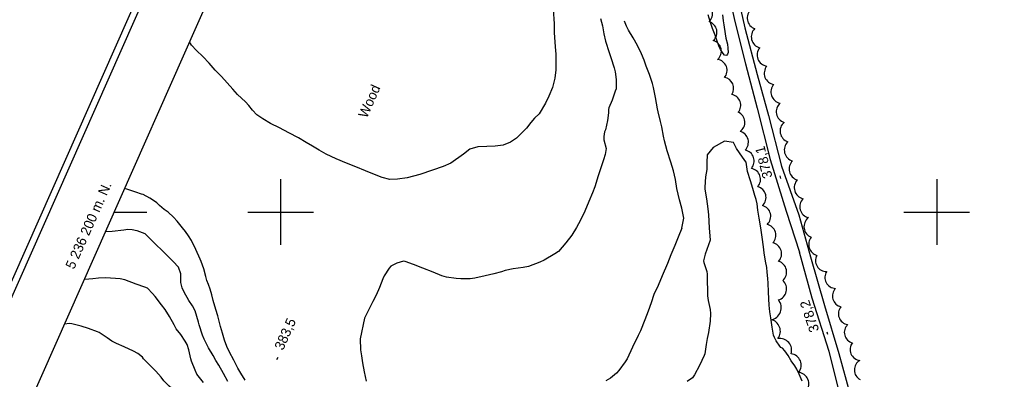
# Model space of a CAD drawing. Extents: x 287698 to 290158, y 5234163 to 5237182.
# Drawn here: x 288320.4 to 288616.1, y 5236148.9 to 5236258.8 of the extents above; entities that cross this region are included whole.
import ezdxf

# ---------------------------------------------------------------- set-up
doc = ezdxf.new("R2010")
doc.units = 0
for name, color, linetype in [('Niveau 1', 7, 'Continuous'), ('Niveau 19', 7, 'Continuous'), ('Niveau 2', 7, 'Continuous'), ('Niveau 3', 7, 'Continuous'), ('Niveau 44', 7, 'Continuous'), ('Niveau 60', 7, 'Continuous'), ('Niveau 61', 7, 'Continuous')]:
    doc.layers.add(name, color=color, linetype=linetype)

msp = doc.modelspace()

# ---------------------------------------------------------------- linework, layer by layer
at = {"layer": 'Niveau 1'}
for points in [[(288534.72, 5236260.25), (288534.91, 5236258.33), (288535.1, 5236257.1), (288535.48, 5236254.44), (288535.74, 5236253.1), (288536.18, 5236251.2), (288536.33, 5236249.99), (288536.38, 5236248.73), (288536.2, 5236248.19), (288535.88, 5236247.74), (288535.34, 5236247.84), (288534.88, 5236248.4), (288534.13, 5236249.61), (288533.62, 5236250.69), (288532.93, 5236252.42), (288532.41, 5236253.98), (288531.66, 5236256.01), (288530.93, 5236258.13), (288530.27, 5236260.25)], [(288522.32, 5236195.12), (288522.93, 5236198.1), (288522.25, 5236201.2), (288521.58, 5236203.71), (288520.78, 5236207.22), (288520.32, 5236209.96), (288519.72, 5236212.64), (288518.98, 5236215.22), (288517.8, 5236218.65), (288516.98, 5236221.74), (288516.71, 5236223.13), (288516.23, 5236226.05), (288515.83, 5236227.65), (288515.03, 5236230.64), (288514.89, 5236231.52), (288514.27, 5236235.01), (288513.7, 5236238), (288513.37, 5236239.23), (288512.39, 5236242), (288511.44, 5236244.53), (288510.86, 5236246.34), (288510.02, 5236248.34), (288508.79, 5236250.83), (288507.44, 5236253.16), (288506.05, 5236255.48), (288505.46, 5236256.78), (288504.83, 5236258.24)], [(288522.32, 5236195.12), (288521.19, 5236192.34), (288520.13, 5236189.76), (288518.98, 5236186.94), (288517.89, 5236184.28), (288516.33, 5236180.53), (288515.04, 5236177.63), (288513.76, 5236174.8), (288512.94, 5236172.31), (288511.99, 5236169.78), (288510.99, 5236167.09), (288509.71, 5236163.8), (288509, 5236162.3), (288507.29, 5236158.74), (288505.62, 5236155.22), (288505, 5236154.26), (288503.13, 5236151.62), (288502.38, 5236150.82), (288500.53, 5236149.36), (288499.11, 5236148.54)], [(288346.56, 5236194.05), (288348.62, 5236194.21), (288352.22, 5236194.55), (288353.37, 5236194.77), (288354.78, 5236194.69), (288356.15, 5236194.36), (288358.61, 5236193.49), (288367.23, 5236184.96)], [(288383.86, 5236148.34), (288382.57, 5236150.76), (288381.17, 5236153.28), (288380.2, 5236154.74), (288379.4, 5236156.22), (288378.03, 5236158.6), (288376.72, 5236161.19), (288376.2, 5236162.43), (288375.11, 5236165.63), (288374.92, 5236166.41), (288373.92, 5236169.86), (288373.08, 5236171.39), (288372.01, 5236173.01), (288370.6, 5236175.51), (288369.97, 5236176.92), (288369.58, 5236178.49), (288369.56, 5236181.16), (288368.87, 5236183.24), (288367.23, 5236184.96)]]:
    msp.add_lwpolyline(points, dxfattribs=at)
at = {"layer": 'Niveau 19'}
for points in [[(288518.52, 5236482.17), (288518.51, 5236469.32), (288517.92, 5236453.86), (288517.66, 5236437.54), (288517.23, 5236421.32), (288517.22, 5236403.64), (288518.39, 5236388.14), (288519.01, 5236373.22), (288520.62, 5236356.96), (288521.68, 5236343.74), (288523.2, 5236324.51), (288526.18, 5236307.64), (288529.13, 5236294.92), (288532.36, 5236282.96), (288535.67, 5236270.53), (288538.48, 5236258.13), (288541.67, 5236245.25), (288545.24, 5236231.69), (288549.17, 5236216.09), (288554.11, 5236200.24), (288558.19, 5236187.81)], [(288521.3, 5236480.92), (288520.93, 5236467.19), (288520.46, 5236451.28), (288519.89, 5236435.79), (288519.6, 5236421.45), (288519.87, 5236405.37), (288520.97, 5236389.91), (288521.87, 5236372.23), (288522.99, 5236355.92), (288524.29, 5236339.04), (288526.08, 5236323.71), (288528.12, 5236311.11), (288530.98, 5236297.47), (288534.85, 5236283.63), (288538.06, 5236271.56), (288541.5, 5236256.24), (288545.27, 5236242), (288548.74, 5236229.5), (288552.67, 5236214.05), (288558.01, 5236199.12), (288561.49, 5236186.39)], [(288579.45, 5235966.21), (288590.48, 5235970.55), (288599.56, 5235973.1), (288608.8, 5235975.7), (288611.76, 5235977.65), (288611, 5235981.11), (288607.75, 5235989.15), (288602.54, 5236003.05), (288600.44, 5236015.05), (288597.95, 5236030.93), (288595.07, 5236045.76), (288591.11, 5236062.15), (288585.16, 5236080.73), (288580.85, 5236098.75), (288577.18, 5236115.66), (288572.06, 5236138.02), (288567.19, 5236157.42), (288562.05, 5236173.75), (288558.19, 5236187.81)], [(288561.49, 5236186.39), (288565.78, 5236171.53), (288570.11, 5236156.8), (288574.67, 5236140.56)]]:
    msp.add_lwpolyline(points, dxfattribs=at)
at = {"layer": 'Niveau 2'}
for points in [[(288483.03, 5236261.92), (288483.34, 5236257.49), (288483.38, 5236254.85), (288483.67, 5236250.39), (288483.87, 5236248.22), (288483.87, 5236243.38), (288483.6, 5236240.9), (288482.85, 5236238), (288481.77, 5236235.34), (288480.72, 5236233.27), (288478.77, 5236229.97), (288477.4, 5236228.67), (288476.27, 5236227.37), (288474.99, 5236225.65), (288471.93, 5236222.55), (288470.02, 5236221.35), (288467.81, 5236220.45), (288465.4, 5236220.07), (288462.84, 5236219.99), (288460.15, 5236219.91), (288457.68, 5236219.19), (288455.69, 5236217.63), (288451.9, 5236214.93), (288449.57, 5236213.92), (288446.28, 5236212.77), (288442.39, 5236211.5), (288438.56, 5236210.42), (288435.65, 5236210.04), (288433.28, 5236209.96), (288430.97, 5236210.58), (288428.61, 5236211.48)], [(288497.51, 5236259.04), (288498.12, 5236256.83), (288498.54, 5236254.36), (288499.03, 5236252.17), (288500.11, 5236248.71), (288500.68, 5236247.13), (288501.7, 5236244.06), (288502, 5236242.82), (288502.25, 5236240.47), (288502.28, 5236237.64), (288501.98, 5236236.91), (288501.03, 5236234.12), (288500.08, 5236231.81), (288499.9, 5236231.35)], [(288428.61, 5236211.48), (288425.9, 5236212.59), (288422.95, 5236213.76), (288420.04, 5236214.95), (288416.89, 5236216.24), (288413.82, 5236217.66), (288411.7, 5236218.85), (288409.74, 5236220.13), (288407.78, 5236221.21), (288405.41, 5236222.64), (288402.5, 5236224.21), (288399.64, 5236225.74), (288396.91, 5236227), (288394.59, 5236228.44), (288392.78, 5236229.72), (288391.39, 5236231.12), (288390.34, 5236232.54), (288389.24, 5236233.6), (288386.89, 5236235.91), (288385.45, 5236237.56), (288381.93, 5236241.34), (288380.02, 5236243.32), (288378.19, 5236245.49), (288376.24, 5236247.47), (288374.32, 5236249.28), (288372.84, 5236250.98), (288372.22, 5236252.01)], [(288499.9, 5236231.35), (288499.89, 5236230.3), (288499.62, 5236227.94), (288499.03, 5236225.08), (288498.74, 5236224.52), (288498.51, 5236223.02), (288498.54, 5236222.01), (288499.19, 5236219.37), (288498.9, 5236217.57), (288498.38, 5236215.99), (288496.83, 5236211.08), (288495.78, 5236207.74), (288495.08, 5236205.87), (288493.92, 5236203.18), (288492.68, 5236200.26), (288491.38, 5236197.55), (288490.22, 5236195.31), (288488.74, 5236192.97), (288486.97, 5236190.58), (288484.71, 5236188.02), (288483.6, 5236187.29), (288480.37, 5236185.34), (288478.99, 5236184.69), (288475.53, 5236183.44), (288473.96, 5236183.13), (288470.86, 5236182.69), (288468.39, 5236182.21), (288467.32, 5236181.77), (288464.94, 5236181.12), (288462.38, 5236180.59), (288459.22, 5236179.87), (288457.75, 5236179.67), (288454.95, 5236179.64), (288453.45, 5236179.73), (288450.55, 5236180.15), (288449.17, 5236180.55), (288446.46, 5236181.66)], [(288541.91, 5236215.21), (288541.84, 5236215.29), (288540.79, 5236216.71), (288538.97, 5236219.43), (288538.08, 5236221.27), (288535.28, 5236221.69), (288531.85, 5236219.73)], [(288531.85, 5236219.73), (288529.98, 5236217.46), (288529.9, 5236215.16), (288529.88, 5236213), (288529.46, 5236210.76), (288529.34, 5236207.58), (288529.32, 5236206.98), (288529.78, 5236204.04), (288530.26, 5236200.97), (288530.4, 5236199.14), (288530.63, 5236195.15), (288530.92, 5236191.47), (288530.47, 5236189.99), (288529.38, 5236187.17), (288528.91, 5236185.15), (288528.99, 5236184.57), (288529.87, 5236181.85), (288530.02, 5236181.05), (288530.05, 5236178.95), (288530.13, 5236176.13), (288530.08, 5236174.39), (288530.27, 5236172.97), (288530.88, 5236170.31), (288530.99, 5236169.03), (288530.93, 5236166.67), (288530.42, 5236163.23), (288530, 5236161.42), (288529.72, 5236159.56), (288529.29, 5236156.72), (288529.1, 5236156.26), (288527.63, 5236153.14), (288526.2, 5236150.36), (288525.57, 5236149.44), (288523.94, 5236148.33)], [(288550.27, 5236162.42), (288549.82, 5236164.92), (288549.65, 5236166.28), (288549.38, 5236167.7), (288549.1, 5236169.6), (288548.9, 5236171.63), (288548.78, 5236173.51), (288548.71, 5236175.68), (288548.63, 5236178.26), (288548.47, 5236179.72), (288548.34, 5236181.63), (288548.16, 5236183.04), (288547.83, 5236185.03), (288547.41, 5236187.55), (288547.21, 5236189.39), (288546.79, 5236192.38), (288546.33, 5236195.23), (288545.89, 5236198.15), (288545.49, 5236200.56), (288545.21, 5236202.51), (288544.93, 5236203.81), (288544.59, 5236205.07), (288543.97, 5236207.21), (288543.24, 5236209.58), (288542.35, 5236212.4), (288542.06, 5236213.78), (288541.91, 5236215.21)], [(288389.13, 5236148.7), (288387.81, 5236150.83), (288386.98, 5236152.41), (288385.7, 5236154.82), (288384.41, 5236157.2), (288383.58, 5236159), (288382.83, 5236160.96), (288382.23, 5236163.01), (288381.7, 5236165.11), (288380.89, 5236168.3), (288380.28, 5236170.3), (288379.44, 5236173.03), (288379.01, 5236174.79), (288378.54, 5236176.52), (288377.96, 5236177.85), (288377.48, 5236179.16), (288377.16, 5236180.38), (288376.53, 5236182.63), (288375.81, 5236184.93), (288375.47, 5236185.65), (288374.09, 5236188.57), (288372.77, 5236191.32), (288371.89, 5236192.74), (288371, 5236194.03), (288370.07, 5236195.22), (288368.47, 5236197.22), (288367.31, 5236198.44), (288365.67, 5236200.01), (288364.51, 5236200.83), (288363.02, 5236201.96), (288362.23, 5236202.83), (288361.23, 5236203.58), (288360.08, 5236204.21), (288358.1, 5236205.34), (288357.6, 5236205.48), (288355.84, 5236206.1), (288353.1, 5236207.03), (288352.37, 5236207.17)], [(288446.46, 5236181.66), (288443.34, 5236182.9), (288440.54, 5236184.02), (288437.94, 5236184.96), (288437.44, 5236185), (288435.46, 5236184.46), (288433.56, 5236183.49), (288433.04, 5236182.93), (288431.54, 5236180.59), (288431.13, 5236179.67), (288430.09, 5236176.96), (288429.14, 5236174.63), (288428.14, 5236172.76)], [(288376.47, 5236147.97), (288374.46, 5236150.58), (288373.91, 5236151.74), (288372.81, 5236154.53), (288372.62, 5236155.25), (288372.03, 5236157.95), (288371.5, 5236159.55), (288370.9, 5236160.65), (288369.57, 5236162.67), (288368.19, 5236164.36), (288367.55, 5236165.55), (288366.14, 5236168.11), (288364.78, 5236170.23), (288363.68, 5236171.74), (288361.77, 5236174.25), (288360.95, 5236175.17), (288359.36, 5236176.75), (288358.56, 5236177.07), (288355.93, 5236178.02), (288352.48, 5236179.34), (288351.04, 5236179.67), (288349.67, 5236179.75), (288346.56, 5236179.93), (288344.49, 5236179.88), (288342.75, 5236179.6), (288340.29, 5236179.39), (288340.08, 5236179.4)], [(288428.14, 5236172.76), (288425.6, 5236167.59), (288424.28, 5236161.27), (288424.31, 5236157.96), (288424.68, 5236156.15), (288424.97, 5236154.04), (288425.43, 5236151.29), (288426.1, 5236148.35)], [(288372.51, 5236141.2), (288371.89, 5236141.71), (288369.73, 5236143.39), (288368.41, 5236144.7), (288366.04, 5236146.83), (288364.4, 5236148.52), (288363.57, 5236149.63), (288361.97, 5236151.44), (288360.13, 5236153.28), (288358.2, 5236155.22), (288357.86, 5236155.71), (288356.42, 5236156.8), (288355.15, 5236157.53), (288352.28, 5236158.89), (288349.94, 5236159.91), (288348.56, 5236160.62), (288347.06, 5236161.67), (288344.67, 5236163.25), (288344.12, 5236163.47), (288341.46, 5236164.47), (288339.19, 5236165.2), (288336.35, 5236165.91), (288335.64, 5236165.99), (288334.07, 5236165.83)], [(288559.02, 5236148.37), (288558.08, 5236150.53), (288557.3, 5236152.09), (288556.7, 5236153.07), (288555.64, 5236154.62), (288554.7, 5236156.2), (288553.67, 5236157.69), (288552.95, 5236158.47), (288552.48, 5236158.69), (288552.14, 5236159.12), (288551.1, 5236160.66), (288550.53, 5236161.69), (288550.27, 5236162.42)]]:
    msp.add_lwpolyline(points, dxfattribs=at)
at = {"layer": 'Niveau 3'}
for p, q in [((288552.44, 5236210.3), (288552.24, 5236211.07)), ((288566.79, 5236162.62), (288566.57, 5236163.38)), ((288398.88, 5236154.97), (288399.2, 5236155.7))]:
    msp.add_line(p, q, dxfattribs=at)
at = {"layer": 'Niveau 44'}
for centre, radius, start, end in [((288542.9, 5236209.98), 3.39, 318.2784, 80.0001), ((288549.33, 5236187.27), 3.39, 316.7512, 78.4652), ((288573.34, 5236168.96), 3.34, 139.6968, 261.3924), ((288555.16, 5236153.29), 3.51, 320.9504, 82.7219), ((288578.24, 5236151.83), 3.35, 120.1029, 242.0479)]:
    msp.add_arc(centre, radius, start, end, dxfattribs=at)
for centre, major_axis, ratio, start_param, end_param in [((288528.29, 5236260.59), (3.36, -0.3), 0.99996, 5.549195, 7.677495), ((288545.63, 5236259.24), (-3.36, -0.66), 0.998567, 5.219281, 7.345445), ((288529.63, 5236254.87), (3.3, 0.76), 0.998148, 5.217877, 7.343451), ((288546.92, 5236253.47), (-3.34, -0.84), 0.99995, 5.21833, 7.343444), ((288530.95, 5236249.11), (3.34, 0.57), 0.998798, 5.273534, 7.402736), ((288548.67, 5236247.97), (-3.2, -1.26), 0.998583, 5.220129, 7.345677), ((288532.79, 5236243.26), (-0.33, 3.34), 0.979824, 3.899245, 6.056386), ((288550.84, 5236242.35), (-3.31, -0.91), 0.999596, 5.31569, 7.443867), ((288534.8, 5236237.74), (0.09, 3.36), 0.979201, 4.161248, 6.165415), ((288552.88, 5236236.63), (2.59, -2.25), 0.999995, 3.114454, 5.245032), ((288536.95, 5236232.62), (-1.26, 3.11), 0.981393, 3.632613, 5.709599), ((288554.51, 5236230.66), (-3.4, -0.58), 0.997435, 5.259842, 7.377239), ((288538.14, 5236227.38), (3.35, 0.32), 0.99852, 5.217452, 7.341748), ((288539.21, 5236221.33), (3.33, 0.62), 0.999239, 5.295321, 7.420941), ((288555.68, 5236224.75), (-3.37, -0.66), 0.999729, 5.218968, 7.349728), ((288540.98, 5236215.58), (3.27, 0.85), 0.999364, 5.29805, 7.428256), ((288556.97, 5236218.96), (-3.34, -0.82), 0.999729, 5.221515, 7.349362), ((288558.42, 5236213.14), (-3.36, -0.72), 0.99743, 5.257196, 7.382093), ((288560, 5236207.44), (-3.3, -0.98), 0.999063, 5.221527, 7.345419), ((288544.59, 5236204.46), (-2.39, 2.39), 0.999994, 3.114054, 5.245454), ((288561.67, 5236201.65), (-3.3, -0.94), 0.999644, 5.217304, 7.347097), ((288546.01, 5236198.74), (3.29, 0.81), 0.999977, 5.21798, 7.344458), ((288562.99, 5236195.57), (-3.44, -0.36), 0.997907, 5.26155, 7.387393), ((288547.58, 5236192.94), (3.32, 0.65), 0.999582, 5.321474, 7.44312), ((288564.26, 5236190.08), (0.89, -3.29), 0.964643, 3.726938, 5.763379), ((288566.36, 5236185.2), (2.46, -2.23), 0.999619, 3.37659, 5.472902), ((288550.83, 5236181.68), (3.39, 0.44), 0.999489, 5.311676, 7.435466), ((288569.24, 5236180.05), (-3.09, -1.29), 0.999471, 5.304741, 7.436247), ((288550.75, 5236176.55), (3.4, -0.79), 0.999461, 5.218024, 7.343968), ((288571.52, 5236174.36), (-3.25, -0.69), 0.999214, 5.292309, 7.421763), ((288548.9, 5236170.81), (3.06, -2.07), 0.999938, 5.458608, 7.583569), ((288549.09, 5236163.77), (-1.2, 3.25), 0.925516, 3.636038, 5.78874), ((288575.12, 5236163.28), (-3.18, -0.85), 0.996797, 5.215306, 7.337245), ((288552.44, 5236158.06), (-2.24, 2.64), 0.935444, 3.648403, 5.804191), ((288576.91, 5236158.05), (-3.07, -1.31), 0.999947, 5.216399, 7.345512), ((288557.51, 5236147.61), (3.21, 1.36), 0.999565, 5.217575, 7.346671)]:
    msp.add_ellipse(centre, major_axis=major_axis, ratio=ratio, start_param=start_param, end_param=end_param, dxfattribs=at)
at = {"layer": 'Niveau 60'}
for points in [[(289088.15, 5234163.34), (287698.12, 5234778.71), (288762.01, 5237181.96), (290152.07, 5236566.6), (289088.15, 5234163.34)], [(289087.13, 5234165.98), (287700.76, 5234779.73), (288763.06, 5237179.33), (290149.43, 5236565.58), (289087.13, 5234165.98)]]:
    msp.add_lwpolyline(points, dxfattribs=at)
msp.add_lwpolyline([(289077.96, 5234189.73), (287724.51, 5234788.9), (288562.53, 5236681.9), (289915.99, 5236082.74)], close=True, dxfattribs=at)
at = {"layer": 'Niveau 61'}
msp.add_line((288349.2, 5236200), (288359.2, 5236200), dxfattribs=at)
for points in [[(288400, 5236210), (288400, 5236200), (288400, 5236190)], [(288600, 5236210), (288600, 5236200), (288600, 5236190)], [(288390, 5236200), (288400, 5236200), (288410, 5236200)], [(288590, 5236200), (288600, 5236200), (288610, 5236200)]]:
    msp.add_lwpolyline(points, dxfattribs=at)

# ---------------------------------------------------------------- texts
at = {"layer": 'Niveau 3'}
for s, rotation, p in [('378,1', 104.5551, (288549.96, 5236210.71)), ('378,2', 108.5572, (288564.22, 5236163.92)), ('383,5', 66.1217, (288400.72, 5236157.6))]:
    msp.add_text(s, height=3, rotation=rotation, dxfattribs=at).set_placement(p)
at = {"layer": 'Niveau 44'}
msp.add_text('Wood', height=3, rotation=66.1212, dxfattribs=at).set_placement((288426.27, 5236228.44))
at = {"layer": 'Niveau 61'}
msp.add_text('5 236 200 m. N.', height=3, rotation=66.1213, dxfattribs=at).set_placement((288337.01, 5236182.35))

doc.saveas('drawing.dxf')
